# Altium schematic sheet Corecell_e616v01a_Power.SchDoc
size B; DrawnBy: Erik Fountain; DocumentNumber: 4; SheetNumber: 4; SheetTotal: 5; PageSetup: Record=PageOptions¦CenterHorizontal=True¦CenterVertical=True¦PrintScale=0.72¦XCorrection=1.00¦YCorrection=1.00¦PrintKind=0¦BorderSize=5000000¦LeftOffset=0¦BottomOffset=0¦Orientation=2¦PaperLength=1000¦PaperWidth=1000¦Scale=100¦PaperSource=7¦PrintQuality=-4¦MediaType=1¦DitherType=10¦PaperKind=Letter¦PrintScaleMode=1
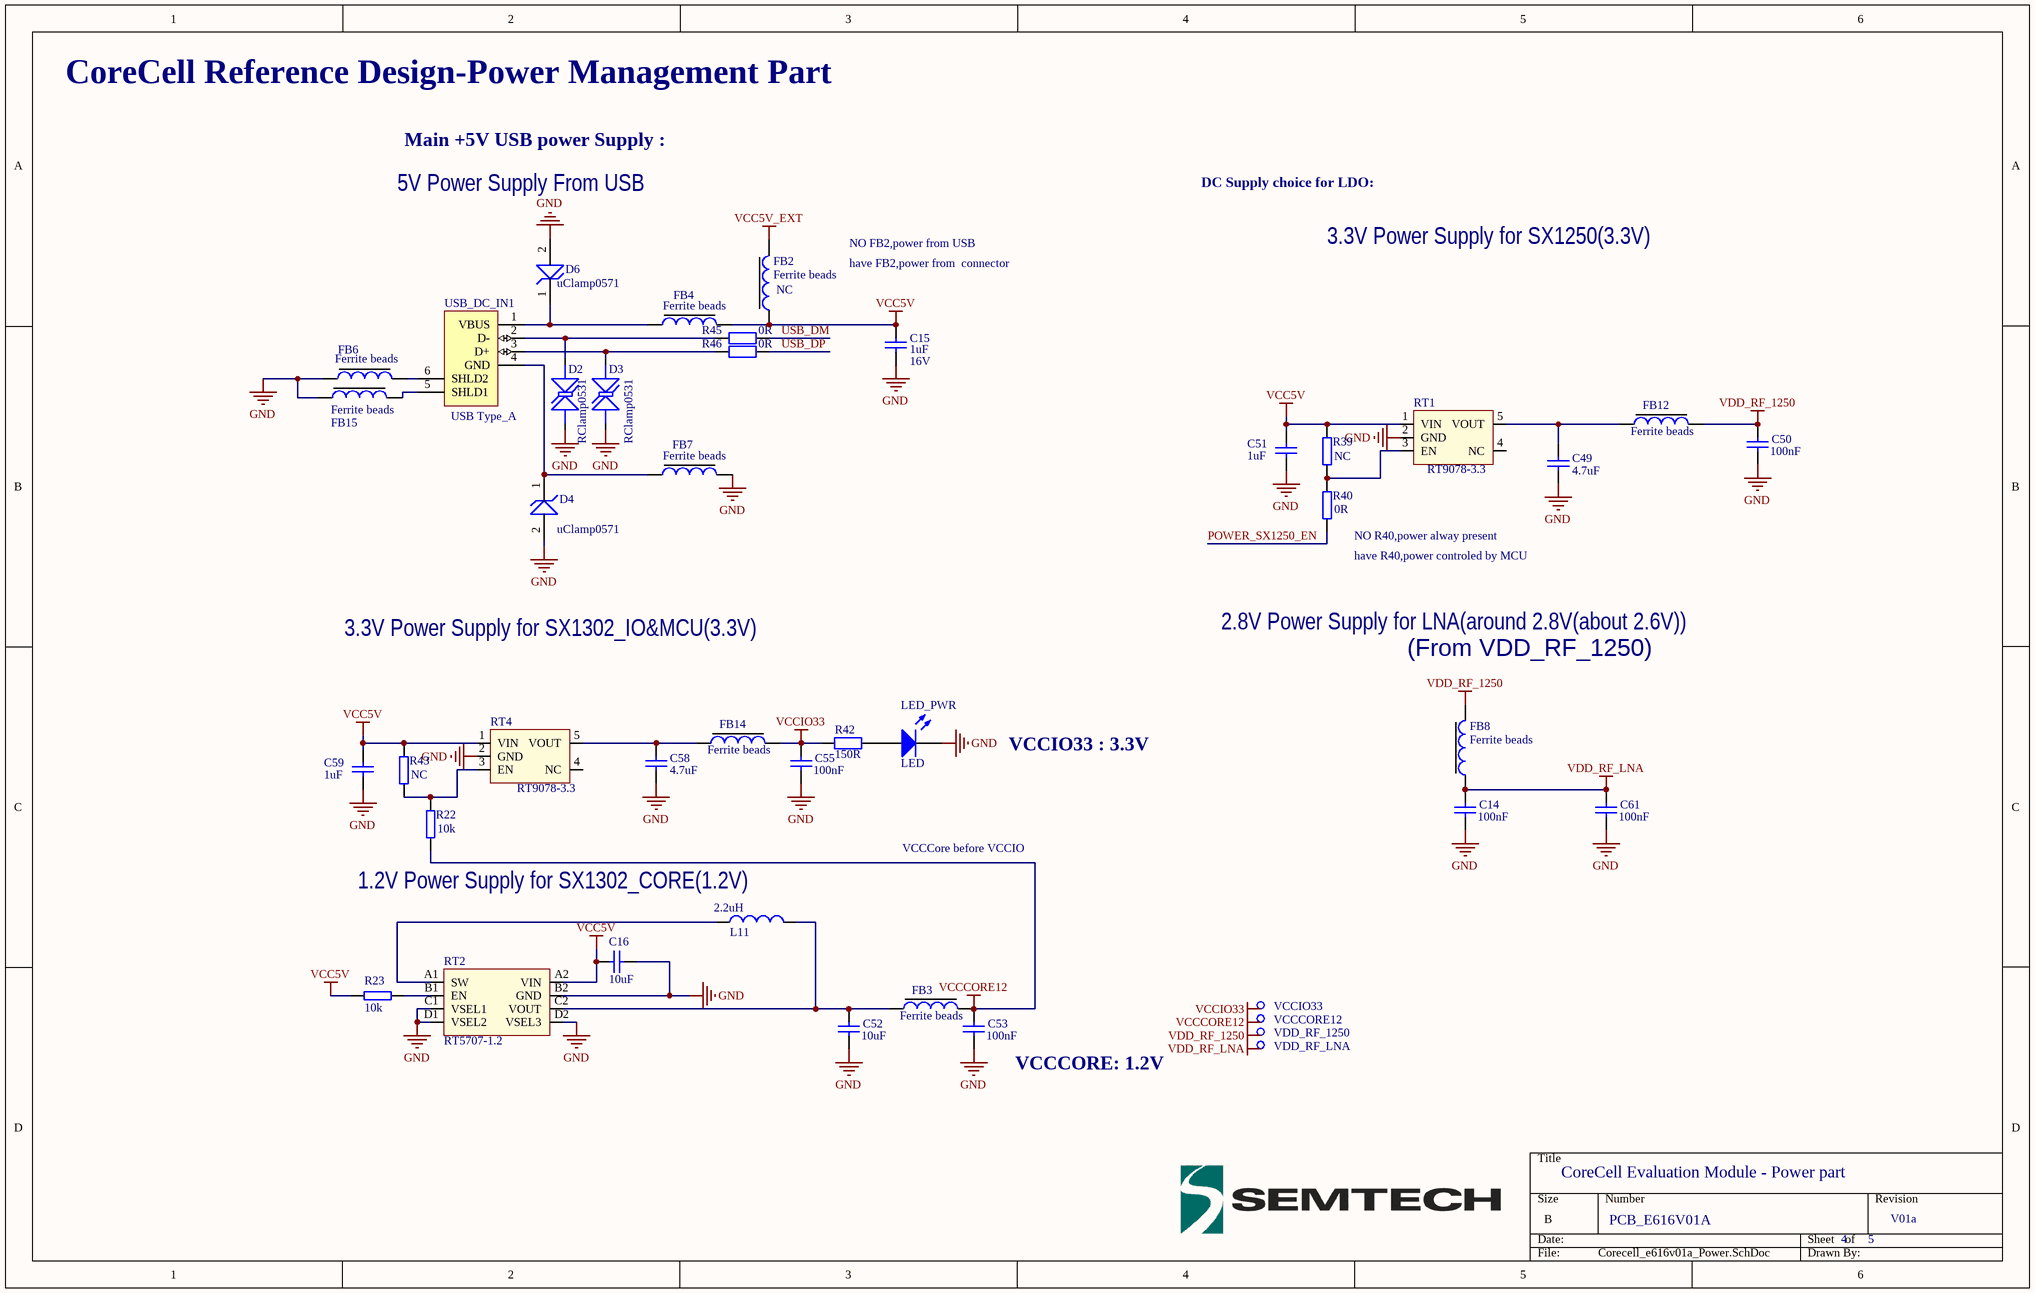
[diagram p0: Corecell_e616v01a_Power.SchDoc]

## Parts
C14  value 100nF  [rlc_402_smd_small]  (hidden comment: Cap)
C15  value 1uF  DC Voltage: 16V  [rlc_805_smd]  (hidden comment: Cap)
C16  value 10uF  [rlc_402_smd_small]  (hidden comment: Cap)
C49  value 4.7uF  [rlc_402_smd_small]  (hidden comment: Cap)
C50  value 100nF  [rlc_402_smd_small]  (hidden comment: Cap)
C51  value 1uF  [rlc_402_smd_small]  (hidden comment: Cap)
C52  value 10uF  [rlc_402_smd_small]  (hidden comment: Cap)
C53  value 100nF  [rlc_402_smd_small]  (hidden comment: Cap)
C55  value 100nF  [rlc_402_smd_small]  (hidden comment: Cap)
C58  value 4.7uF  [rlc_402_smd_small]  (hidden comment: Cap)
C59  value 1uF  [rlc_402_smd_small]  (hidden comment: Cap)
C61  value 100nF  [rlc_402_smd_small]  (hidden comment: Cap)
D2  RClamp0531  [SLP1006P2T]
D3  RClamp0531  [SLP1006P2T]
D4  uClamp0571  [1610]
D6  uClamp0571  [1610]
FB2  Ferrite beads  value NC  [rlc_402_smd_small]
FB3  Ferrite beads  [rlc_402_smd_small]
FB4  Ferrite beads  [rlc_402_smd_small]
FB6  Ferrite beads  [rlc_402_smd_small]
FB7  Ferrite beads  [rlc_402_smd_small]
FB8  Ferrite beads  [rlc_402_smd_small]
FB12  Ferrite beads  [rlc_402_smd_small]
FB14  Ferrite beads  [rlc_402_smd_small]
FB15  Ferrite beads  [rlc_402_smd_small]
L11  value 2.2uH  [2520]  (hidden comment: Inductor)
LED_PWR  LED  [CD1608-0603]
R22  value 10k  [rlc_402_smd_small]  (hidden comment: Resistor)
R23  value 10k  [rlc_402_smd_small]  (hidden comment: Resistor)
R39  value NC  [rlc_402_smd_small]  (hidden comment: Resistor)
R40  value 0R  [rlc_402_smd_small]  (hidden comment: Resistor)
R42  value 150R  [rlc_402_smd_small]  (hidden comment: Resistor)
R43  value NC  [rlc_402_smd_small]  (hidden comment: Resistor)
R45  value 0R  [rlc_402_smd_small]  (hidden comment: Resistor)
R46  value 0R  [rlc_402_smd_small]  (hidden comment: Resistor)
RT1  RT9078-3.3  [TSOT-23-5]
RT2  value RT5707-1.2  [CSP_8]  (hidden comment: RT5707)
RT4  RT9078-3.3  [TSOT-23-5]
USB_DC_IN1  value USB Type_A  [Keystone USB Type 931]  (hidden comment: USB Type-A SMD)
VCCCORE12  Test Pin  [PIN_SMD]  (value not drawn)
VCCIO33  Test Pin  [PIN_SMD]  (value not drawn)
VDD_RF_1250  Test Pin  [PIN_SMD]  (value not drawn)
VDD_RF_LNA  Test Pin  [PIN_SMD]  (value not drawn)

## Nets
GND: C14.1 C15.2 C16.2 C49.2 C50.1 C51.2 C52.1 C53.1 C55.1 C58.2 C59.2 C61.1 D2.2(K) D3.2(K) D4.2 D6.2 FB6.1 FB7.2 FB15.1 LED_PWR.2(K) RT1.2(GND) RT2.B2(GND) RT2.C1(VSEL1) RT2.D1(VSEL2) RT2.D2(VSEL3) RT4.2(GND)
VCC5V: C15.1 C16.1 C51.1 C59.1 FB2.1 FB4.2 R23.1 R39.1 R43.1 RT1.1(VIN) RT2.A2(VIN) RT4.1(VIN)
VCC5V_EXT: FB2.2
VCCCORE12: C53.2 FB3.2 R22.2 VCCCORE12.1(pin)
VCCIO33: C55.2 FB14.2 R42.1 VCCIO33.1(pin)
VDD_RF_1250: C50.2 FB8.2 FB12.2 VDD_RF_1250.1(pin)
VDD_RF_LNA: C14.2 C61.2 FB8.1 VDD_RF_LNA.1(pin)
POWER_SX1250_EN: R40.2
USB_DM: R45.2
USB_DP: R46.2
NetC49_1: C49.1 FB12.1 RT1.5(VOUT)
NetC52_2: C52.2 FB3.1 L11.2 RT2.C2(VOUT)
NetC58_1: C58.1 FB14.1 RT4.5(VOUT)
NetD2_1: D2.1(A) R45.1 USB_DC_IN1.2(D-)
NetD3_1: D3.1(A) R46.1 USB_DC_IN1.3(D+)
NetD4_1: D4.1 FB7.1 USB_DC_IN1.4(GND)
NetD6_1: D6.1 FB4.1 USB_DC_IN1.1(VBUS)
NetFB6_2: FB6.2 USB_DC_IN1.6(SHLD2)
NetFB15_2: FB15.2 USB_DC_IN1.5(SHLD1)
NetL11_1: L11.1 RT2.A1(SW)
NetLED_PWR_1: LED_PWR.1(A) R42.2
NetR22_1: R22.1 R43.2 RT4.3(EN)
NetR23_2: R23.2 RT2.B1(EN)
NetR39_2: R39.2 R40.1 RT1.3(EN)

Not connected (* = marked no-connect by the designer): RT1 4(NC); RT4 4(NC)

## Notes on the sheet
- CoreCell Reference Design-Power Management Part
- Main +5V USB power Supply :
- 5V Power Supply From USB
- DC Supply choice for LDO:
- NO FB2,power from USB
- have FB2,power from  connector
- 3.3V Power Supply for SX1250(3.3V)
- (near R40) NO R40,power alway present
- (near R40) have R40,power controled by MCU
- 3.3V Power Supply for SX1302_IO&MCU(3.3V)
- 2.8V Power Supply for LNA(around 2.8V(about 2.6V))
- (From VDD_RF_1250)
- VCCIO33 : 3.3V
- 1.2V Power Supply for SX1302_CORE(1.2V)
- VCCCore before VCCIO
- (near C53) VCCCORE: 1.2V
- CoreCell Evaluation Module - Power part
- PCB_E616V01A
- V01a

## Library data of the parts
C14-C16 C49-C53 C55 C58 C59 C61 = Cap: Capacitor SMD
D2 D3 = RClamp0531T: Ultra Low Capacitance 1-line ESD Protection
D4 D6 = uClamp0571: Unidirectional,Ultra Low Capacitance 1-line ESD Protection
FB3 FB4 FB6-FB8 FB12 FB14 FB15 = Ferrite beads: Value: 10R @100MHz
L11 = Inductor: Code_IEC: 1005
LED_PWR = LED: Value: Red_0603
R22 R23 R39 R40 R43 = Res: SMD Resistor
R42 R45 R46 = Resistor: Resistor SMD - IEC symbol version
RT1 RT4 = RT9078: LDO
RT2 = RT5707: DCDC
USB_DC_IN1 = USB Type-A SMD: USB 2.0 SMT, Type A, Receptacle, 4 Position
VCCCORE12 VCCIO33 VDD_RF_1250 VDD_RF_LNA = test_pin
